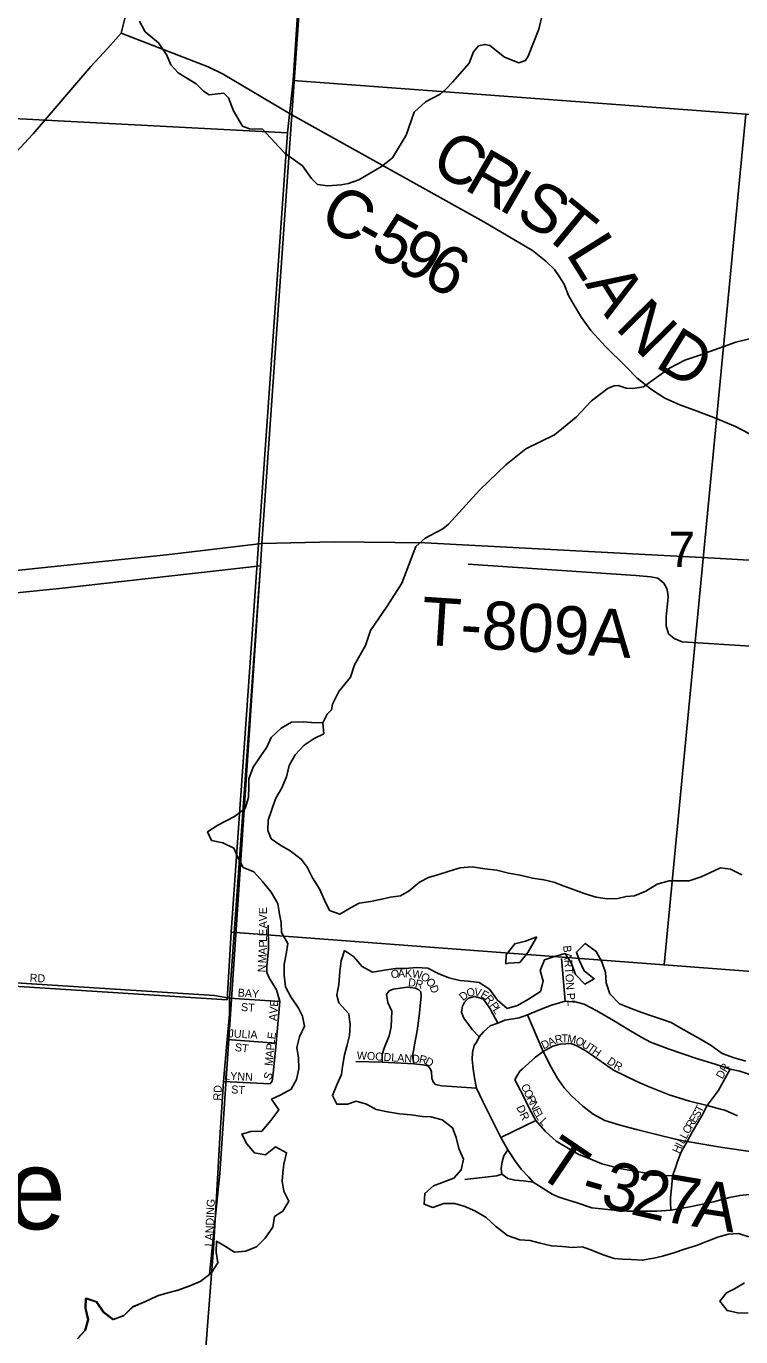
# Model space of a CAD drawing. Extents: x 0 to 40.4, y 0 to 22.
# Drawn here: x 7.886 to 8.731, y 15.17 to 16.72 of the extents above; entities that cross this region are included whole.
import ezdxf

# ---------------------------------------------------------------- set-up
doc = ezdxf.new("R2010")
doc.units = 0
for name, color, linetype in [('GM_X_City_Street', 7, 'Continuous'), ('GM_X_City_Street_Text', 7, 'Continuous'), ('GM_X_Corporation', 7, 'Continuous'), ('GM_X_County_Road', 7, 'Continuous'), ('GM_X_County_Road_Text', 7, 'Continuous'), ('GM_X_Interstate_Route', 7, 'Continuous'), ('GM_X_Major_Lake', 7, 'Continuous'), ('GM_X_Minor_Lake_Text', 7, 'Continuous'), ('GM_X_Minor_River', 7, 'Continuous'), ('GM_X_Section', 7, 'Continuous'), ('GM_X_Section_Text', 7, 'Continuous'), ('GM_X_Township', 7, 'Continuous'), ('GM_X_Township_Road', 7, 'Continuous'), ('GM_X_Township_Road_Text', 7, 'Continuous'), ('GM_X_Township_Subdivision', 7, 'Continuous'), ('GM_X_Township_Subdivision_Text', 7, 'Continuous')]:
    doc.layers.add(name, color=color, linetype=linetype)

msp = doc.modelspace()

# ---------------------------------------------------------------- linework, layer by layer
at = {"layer": 'GM_X_City_Street'}
msp.add_lwpolyline([(7.6176, 15.6748), (7.6167, 15.6381), (7.6129, 15.6192), (7.6135, 15.6152), (7.615, 15.6115), (7.6206, 15.6052), (7.6279, 15.6039), (7.781, 15.5944), (8.1089, 15.5735), (8.127, 15.57)], dxfattribs=at)
at = {"layer": 'GM_X_Corporation'}
msp.add_lwpolyline([(7.6362, 16.0259), (7.9257, 16.0548), (8.1633, 16.0818), (8.1154, 15.3626), (8.103, 15.2433), (8.0922, 15.2349), (8.0793, 15.2296), (8.0649, 15.2244), (8.0506, 15.2206), (8.0407, 15.2177), (8.0267, 15.2109), (8.0123, 15.2049), (8.0013, 15.1943), (7.9888, 15.1898), (7.9775, 15.1986), (7.9692, 15.2107), (7.9567, 15.2149), (7.9563, 15.2032), (7.9593, 15.1895), (7.9558, 15.177), (7.9467, 15.1672)], dxfattribs=at)
at = {"layer": 'GM_X_County_Road'}
for points in [[(7.9986, 16.7119), (8.0034, 16.7309), (8.0048, 16.7445), (8.0043, 16.7815), (8.0046, 16.7931), (8.0078, 16.8426), (8.0237, 17.0971)], [(7.636, 16.0217), (7.6362, 16.0259), (7.6375, 16.0515), (7.6454, 16.1992), (7.6518, 16.3027), (7.6559, 16.3343), (7.6592, 16.3572), (7.6643, 16.369), (7.6877, 16.3975), (7.7254, 16.4327), (7.7742, 16.4712), (7.7928, 16.4863), (7.8207, 16.5131), (7.853, 16.5482), (7.8946, 16.593), (7.9628, 16.6727), (7.983, 16.6943), (7.9986, 16.7119)], [(7.9986, 16.7119), (8.0843, 16.6791), (8.1017, 16.6721), (8.1194, 16.6635), (8.1977, 16.6171)], [(8.1977, 16.6171), (8.2004, 16.6154), (8.4276, 16.4886), (8.485, 16.4547), (8.5009, 16.4422), (8.5112, 16.4323), (8.5163, 16.4248), (8.5223, 16.4149), (8.5278, 16.4018), (8.5348, 16.3895), (8.5429, 16.3755), (8.5541, 16.3602), (8.5712, 16.3412), (8.595, 16.3181), (8.6088, 16.3038), (8.6259, 16.2903), (8.6416, 16.28), (8.6592, 16.2721), (8.6798, 16.2647), (8.7013, 16.2563), (8.725, 16.2467), (8.7589, 16.2289)], [(8.7525, 15.4765), (8.7302, 15.4837), (8.7187, 15.486), (8.7009, 15.4921), (8.6778, 15.4991), (8.6467, 15.5097), (8.6247, 15.5181), (8.6144, 15.5238), (8.5989, 15.5326), (8.581, 15.5437), (8.5613, 15.5553), (8.5461, 15.5631), (8.5372, 15.5653), (8.5235, 15.5668), (8.5077, 15.5621), (8.4935, 15.5565), (8.4792, 15.5503), (8.4691, 15.5471), (8.4524, 15.5442), (8.444, 15.5405), (8.4349, 15.5373), (8.4271, 15.5304), (8.4219, 15.5245), (8.4192, 15.5186), (8.4161, 15.5141), (8.414, 15.5058), (8.4138, 15.4975), (8.4148, 15.4866), (8.4165, 15.4758), (8.419, 15.4635), (8.4264, 15.4479), (8.439, 15.4225), (8.4431, 15.4141), (8.4478, 15.4055), (8.4559, 15.3907), (8.4649, 15.3768), (8.4715, 15.3679), (8.4806, 15.3583), (8.4859, 15.3525), (8.5082, 15.3384), (8.5154, 15.335), (8.5237, 15.3322), (8.5367, 15.3286), (8.5553, 15.322), (8.5816, 15.3193), (8.5974, 15.3181), (8.6321, 15.3182), (8.6488, 15.3193), (8.673, 15.3236), (8.6991, 15.3291), (8.7179, 15.3344), (8.7302, 15.3367), (8.7415, 15.338)]]:
    msp.add_lwpolyline(points, dxfattribs=at)
at = {"layer": 'GM_X_Interstate_Route'}
msp.add_lwpolyline([(7.7959, 16.068), (7.8971, 16.0785), (8.0522, 16.0948), (8.1652, 16.1082), (8.2508, 16.1101), (8.3578, 16.109), (8.7001, 16.0907), (8.8023, 16.0849), (8.8184, 16.0837)], dxfattribs=at)
at = {"layer": 'GM_X_Major_Lake'}
for points in [[(8.7325, 15.7162), (8.7193, 15.7227), (8.7072, 15.7246), (8.6947, 15.7186), (8.6844, 15.7137), (8.6704, 15.7092), (8.6606, 15.7089), (8.6466, 15.7089), (8.6326, 15.7052), (8.619, 15.6969), (8.6057, 15.6913), (8.5959, 15.6906), (8.586, 15.6883), (8.5732, 15.6876), (8.5603, 15.6896), (8.5463, 15.6942), (8.5324, 15.6991), (8.5225, 15.7026), (8.5101, 15.7076), (8.4984, 15.7103), (8.4851, 15.7122), (8.4704, 15.7157), (8.4568, 15.718), (8.4428, 15.7215), (8.4285, 15.7234), (8.4137, 15.7254), (8.3994, 15.7243), (8.3865, 15.7206), (8.3744, 15.7164), (8.3619, 15.7131), (8.3513, 15.7074), (8.3391, 15.6972), (8.3289, 15.6912), (8.3172, 15.6897), (8.3069, 15.6875), (8.2937, 15.6845), (8.2801, 15.6827), (8.2706, 15.6774), (8.2573, 15.6695), (8.2449, 15.6741), (8.2392, 15.6863), (8.2333, 15.6996), (8.225, 15.7125), (8.2186, 15.725), (8.2115, 15.7345), (8.1986, 15.7444), (8.1862, 15.7517), (8.176, 15.7589), (8.1723, 15.7684), (8.1727, 15.7809), (8.1765, 15.7923), (8.1811, 15.8059), (8.1887, 15.8192), (8.1941, 15.8321), (8.1972, 15.8453), (8.2044, 15.8582), (8.215, 15.8695), (8.2268, 15.8774), (8.2382, 15.8831), (8.2371, 15.896), (8.2238, 15.8964), (8.214, 15.8972), (8.2, 15.8969), (8.1879, 15.8897), (8.1761, 15.8788), (8.1708, 15.867), (8.1639, 15.8568), (8.1548, 15.8436), (8.1495, 15.8299), (8.1498, 15.8205), (8.1494, 15.8076), (8.1452, 15.7947), (8.1326, 15.7853), (8.1129, 15.7747), (8.1008, 15.7672), (8.1057, 15.7569), (8.1189, 15.7538), (8.1321, 15.7477), (8.1373, 15.7352), (8.143, 15.7249), (8.1554, 15.7196), (8.166, 15.7082), (8.1761, 15.6956)], [(8.1761, 15.6956), (8.184, 15.6823), (8.1859, 15.6694), (8.1877, 15.6599), (8.1884, 15.6478), (8.1956, 15.6349), (8.194, 15.6223), (8.1913, 15.6102), (8.1916, 15.5973), (8.1931, 15.5837), (8.1995, 15.5719), (8.2085, 15.5582), (8.2133, 15.5487), (8.2156, 15.5369), (8.2095, 15.5244), (8.2064, 15.5119), (8.2082, 15.4994), (8.2089, 15.4865), (8.2059, 15.474), (8.1998, 15.4627), (8.1876, 15.4559), (8.1763, 15.4506), (8.1853, 15.4381), (8.1758, 15.4256), (8.1651, 15.4127), (8.1519, 15.4124), (8.1413, 15.4094), (8.1473, 15.398), (8.1563, 15.387), (8.1692, 15.385), (8.181, 15.3941), (8.1942, 15.3872), (8.1911, 15.3736), (8.1899, 15.3637), (8.1891, 15.3535), (8.191, 15.3417), (8.197, 15.3299), (8.1897, 15.3182), (8.1799, 15.3118), (8.1779, 15.2993), (8.1688, 15.2861), (8.1589, 15.2759), (8.1457, 15.271), (8.1328, 15.2695), (8.1222, 15.2764), (8.1113, 15.2825), (8.1109, 15.2696), (8.1131, 15.2571), (8.1051, 15.2446), (8.093, 15.2352), (8.0801, 15.2299), (8.0657, 15.2247), (8.0513, 15.2209), (8.0415, 15.2179), (8.0274, 15.2111), (8.013, 15.2051), (8.002, 15.1946), (7.9895, 15.1901), (7.9782, 15.1988), (7.97, 15.211), (7.9575, 15.2152), (7.9571, 15.2035), (7.96, 15.1898), (7.9566, 15.1773), (7.9475, 15.1675)], [(8.7372, 15.4955), (8.7233, 15.4997), (8.7093, 15.5047), (8.6961, 15.5142), (8.6837, 15.5218), (8.6738, 15.5272), (8.6606, 15.5348), (8.6489, 15.5413), (8.6365, 15.5459), (8.6233, 15.5501), (8.6101, 15.5547), (8.5976, 15.5597), (8.5878, 15.5636), (8.5765, 15.5754), (8.572, 15.5883), (8.5713, 15.6004), (8.5672, 15.6133), (8.5604, 15.6255), (8.5472, 15.635), (8.537, 15.6248), (8.5403, 15.6153), (8.5463, 15.6024), (8.558, 15.5932), (8.547, 15.5868), (8.5357, 15.5983), (8.5312, 15.6112), (8.5237, 15.623), (8.5112, 15.6196), (8.4991, 15.6155), (8.4942, 15.603), (8.4975, 15.5904), (8.4944, 15.5779), (8.4804, 15.5689), (8.4675, 15.5617), (8.455, 15.558), (8.4437, 15.5679), (8.4343, 15.5808), (8.4219, 15.5888), (8.409, 15.5904), (8.3992, 15.5912), (8.3863, 15.5943), (8.3735, 15.5993), (8.3614, 15.6058), (8.3478, 15.6066), (8.3346, 15.6051), (8.3232, 15.6052), (8.31, 15.6033), (8.296, 15.6011), (8.2835, 15.6076), (8.2734, 15.6194), (8.2628, 15.6266)], [(8.4537, 15.6107), (8.4568, 15.6118), (8.47, 15.6122), (8.4795, 15.6243), (8.4902, 15.6428)], [(8.4902, 15.6428), (8.4769, 15.6376), (8.464, 15.6346), (8.4538, 15.6213), (8.4537, 15.6107)], [(8.2628, 15.6266), (8.259, 15.6145), (8.2571, 15.6016), (8.2559, 15.5865), (8.2539, 15.5739), (8.2561, 15.5645), (8.2678, 15.5515), (8.2693, 15.5386), (8.2685, 15.5261), (8.2654, 15.5132), (8.2627, 15.503), (8.2604, 15.4894), (8.2592, 15.4799), (8.2539, 15.4678), (8.2485, 15.4549), (8.2538, 15.4446), (8.2662, 15.4446), (8.2765, 15.4483), (8.2889, 15.4449), (8.3003, 15.4384), (8.3135, 15.4357), (8.3278, 15.4334), (8.3414, 15.4322), (8.3551, 15.4302), (8.3649, 15.4298), (8.3781, 15.4263), (8.3905, 15.4168), (8.3947, 15.4054), (8.398, 15.3925), (8.4036, 15.3796), (8.4009, 15.3671), (8.3922, 15.3573), (8.368, 15.3482), (8.3577, 15.3392), (8.3569, 15.3263), (8.3671, 15.3225), (8.3803, 15.3273), (8.3932, 15.3273), (8.4049, 15.3238), (8.417, 15.3185), (8.4302, 15.3108), (8.4415, 15.3006), (8.4554, 15.2895), (8.4702, 15.2841), (8.4823, 15.2833), (8.494, 15.2803), (8.5076, 15.2772), (8.5204, 15.2764), (8.5321, 15.2752), (8.5443, 15.2759), (8.556, 15.2717), (8.5688, 15.2663), (8.5816, 15.2621), (8.5915, 15.2613), (8.6017, 15.2609), (8.6149, 15.2601), (8.6285, 15.2627), (8.6387, 15.2649), (8.652, 15.269), (8.6649, 15.2732), (8.6789, 15.2776), (8.6921, 15.2825), (8.7043, 15.2874), (8.7164, 15.2908), (8.7285, 15.2919), (8.7409, 15.2876)], [(8.7358, 15.2334), (8.724, 15.2263), (8.7146, 15.2214), (8.7066, 15.2116), (8.7152, 15.2005), (8.7277, 15.1978), (8.7402, 15.1974)]]:
    msp.add_lwpolyline(points, dxfattribs=at)
at = {"layer": 'GM_X_Minor_River'}
for points in [[(8.0202, 16.7264), (8.027, 16.7138), (8.0428, 16.7005), (8.0526, 16.6861), (8.0575, 16.6744), (8.0662, 16.6652), (8.0873, 16.6519), (8.096, 16.6436), (8.1028, 16.639), (8.1202, 16.6409), (8.1255, 16.6355), (8.1315, 16.62), (8.1421, 16.6021), (8.1504, 16.5987), (8.1659, 16.5983), (8.1851, 16.5774), (8.1923, 16.5702), (8.2131, 16.555), (8.2236, 16.5402), (8.2308, 16.533), (8.2429, 16.5314), (8.2588, 16.5325), (8.2675, 16.534), (8.2796, 16.5386), (8.3064, 16.5541), (8.3197, 16.5646), (8.3356, 16.5915), (8.3451, 16.6184), (8.3584, 16.6306), (8.3758, 16.64), (8.3826, 16.6457), (8.3906, 16.654), (8.4103, 16.6767), (8.4152, 16.69), (8.4213, 16.6972), (8.4285, 16.6987), (8.4345, 16.6975), (8.4519, 16.6838), (8.4689, 16.677), (8.4768, 16.6796), (8.4799, 16.6849), (8.4924, 16.7167), (8.4989, 16.7433)], [(8.2371, 15.896), (8.2424, 15.9061), (8.2473, 15.9114), (8.2485, 15.9179), (8.2561, 15.933), (8.2697, 15.9501), (8.2747, 15.9645), (8.2876, 15.9876), (8.2936, 16.0054), (8.3134, 16.0342), (8.3304, 16.0611), (8.3472, 16.1046), (8.3581, 16.1145), (8.379, 16.1254), (8.3858, 16.1311), (8.4229, 16.1716), (8.4331, 16.1814), (8.4536, 16.2011), (8.4771, 16.22), (8.5111, 16.2367), (8.5365, 16.2578), (8.5547, 16.2768), (8.5744, 16.2919), (8.5816, 16.2949), (8.5865, 16.2953), (8.5959, 16.2919), (8.6039, 16.2915), (8.6163, 16.2937), (8.647, 16.3157), (8.6652, 16.3251), (8.6841, 16.3315), (8.6905, 16.3338), (8.7253, 16.3466), (8.7548, 16.3537)]]:
    msp.add_lwpolyline(points, dxfattribs=at)
at = {"layer": 'GM_X_Section'}
for points in [[(7.3378, 17.2417), (7.7228, 17.2207), (8.2373, 17.1912), (8.202, 16.6562), (8.1953, 16.5941), (7.7054, 16.6198), (7.2909, 16.6427)], [(8.2373, 17.1912), (9.2326, 17.1127), (9.1966, 16.5816), (8.7372, 16.616), (8.202, 16.6562)], [(8.202, 16.6562), (8.7372, 16.616), (8.6406, 15.6095), (8.1289, 15.6484), (8.1953, 16.5941)], [(7.7054, 16.6198), (8.1953, 16.5941), (8.1289, 15.6484), (8.124, 15.5684), (7.6314, 15.5996)], [(8.7372, 16.616), (9.1966, 16.5816), (9.1227, 15.573), (8.6406, 15.6095)]]:
    msp.add_lwpolyline(points, close=True, dxfattribs=at)
at = {"layer": 'GM_X_Township'}
msp.add_lwpolyline([(8.0846, 14.9692), (8.096, 15.1213), (8.108, 15.2741), (8.1112, 15.3285), (8.1141, 15.384), (8.1155, 15.405), (8.1199, 15.4715), (8.1241, 15.5213), (8.1269, 15.5514), (8.127, 15.57), (8.1633, 16.0818), (8.1652, 16.1082), (8.2004, 16.6154), (8.2342, 17.0906), (8.241, 17.1909), (8.1794, 17.1936), (7.7202, 17.2134)], dxfattribs=at)
at = {"layer": 'GM_X_Township_Road'}
for points in [[(8.749, 15.9863), (8.662, 15.9918), (8.6524, 15.9956), (8.646, 16.0013), (8.6429, 16.0107), (8.6429, 16.0213), (8.6442, 16.0333), (8.6453, 16.0446), (8.6451, 16.0489), (8.6438, 16.0548), (8.6402, 16.0613), (8.6334, 16.0671), (8.6251, 16.0686), (8.6072, 16.0704), (8.4089, 16.0836)], [(8.6653, 15.401), (8.654, 15.4033), (8.6317, 15.409), (8.608, 15.4148), (8.5886, 15.42), (8.5705, 15.4254), (8.5569, 15.4329), (8.5447, 15.4423), (8.5309, 15.4549), (8.5224, 15.4641), (8.5141, 15.4758), (8.507, 15.4886), (8.4976, 15.5071), (8.4792, 15.5503)], [(8.8327, 15.3739), (8.8163, 15.3781), (8.7096, 15.3935), (8.6678, 15.4005), (8.6653, 15.401)]]:
    msp.add_lwpolyline(points, dxfattribs=at)
at = {"layer": 'GM_X_Township_Subdivision'}
for points in [[(8.1862, 15.5664), (8.1824, 15.5799), (8.1738, 15.5941), (8.1709, 15.6005), (8.1709, 15.6075), (8.1728, 15.6283), (8.1726, 15.6566)], [(8.5235, 15.5668), (8.5195, 15.617)], [(8.108, 15.2741), (8.1112, 15.3285), (8.1141, 15.384), (8.1155, 15.405), (8.1199, 15.4715), (8.1241, 15.5213), (8.1269, 15.5514), (8.127, 15.57)], [(8.127, 15.57), (8.1862, 15.5664)], [(8.3073, 15.4946), (8.3075, 15.5034), (8.3096, 15.511), (8.3157, 15.5256), (8.3179, 15.5364), (8.3184, 15.5454), (8.3186, 15.555), (8.314, 15.565), (8.3125, 15.5746), (8.3154, 15.5788), (8.3202, 15.5809), (8.3369, 15.5833), (8.3434, 15.5824)], [(8.3434, 15.5824), (8.3469, 15.582), (8.3505, 15.5802), (8.353, 15.5775), (8.3534, 15.5725), (8.3512, 15.5492), (8.3486, 15.5316), (8.3456, 15.5148), (8.3446, 15.5099), (8.3433, 15.502), (8.3448, 15.4924)], [(8.444, 15.5405), (8.4349, 15.5575), (8.429, 15.5661), (8.4263, 15.5695), (8.4165, 15.5722), (8.4094, 15.5703), (8.4045, 15.5656), (8.4022, 15.5609), (8.401, 15.5538), (8.4037, 15.5466), (8.4096, 15.5385), (8.4143, 15.5326), (8.4219, 15.5245)], [(8.1748, 15.4687), (8.1774, 15.4718), (8.1783, 15.481), (8.1819, 15.5171), (8.1862, 15.5664)], [(8.1241, 15.5213), (8.1819, 15.5171)], [(8.4976, 15.5071), (8.5092, 15.5132), (8.5178, 15.5159), (8.5244, 15.5161), (8.5306, 15.5164), (8.5375, 15.5139), (8.548, 15.508), (8.5623, 15.4982), (8.581, 15.4849), (8.6083, 15.4716), (8.6211, 15.466), (8.6467, 15.4557), (8.6706, 15.4484), (8.6915, 15.443), (8.7072, 15.4389)], [(8.2762, 15.4951), (8.3073, 15.4946), (8.3448, 15.4924), (8.3555, 15.4914), (8.3612, 15.4903), (8.364, 15.4868), (8.3656, 15.4829), (8.366, 15.4757), (8.3675, 15.4712), (8.3704, 15.468), (8.378, 15.4664), (8.419, 15.4635)], [(8.6507, 15.3599), (8.6273, 15.3609), (8.6174, 15.3635), (8.5902, 15.3681), (8.567, 15.3741), (8.5511, 15.381), (8.54, 15.3852), (8.5296, 15.3912), (8.513, 15.401), (8.5005, 15.4123), (8.489, 15.4256), (8.4809, 15.441), (8.4735, 15.4558), (8.4642, 15.4735), (8.4665, 15.478), (8.4699, 15.4837), (8.473, 15.4863), (8.4885, 15.5004), (8.4976, 15.5071)], [(8.6488, 15.3193), (8.6483, 15.3283), (8.6483, 15.3342), (8.6496, 15.3494), (8.6507, 15.3599), (8.654, 15.3693), (8.656, 15.3757), (8.661, 15.3883), (8.6678, 15.4005), (8.6739, 15.4118), (8.6854, 15.4308), (8.6915, 15.443), (8.7045, 15.4607), (8.7187, 15.486)], [(8.1199, 15.4715), (8.1748, 15.4687)], [(8.7072, 15.4389), (8.7124, 15.4376), (8.7274, 15.4308)], [(8.4478, 15.4055), (8.489, 15.4256)], [(8.4859, 15.3525), (8.4743, 15.3542), (8.4643, 15.3549), (8.4559, 15.3568), (8.4489, 15.362), (8.4482, 15.3685), (8.449, 15.3765), (8.451, 15.3838), (8.4559, 15.3907)], [(8.4052, 15.3557), (8.4427, 15.3599), (8.4489, 15.362)]]:
    msp.add_lwpolyline(points, dxfattribs=at)

# ---------------------------------------------------------------- texts
at = {"layer": 'GM_X_City_Street_Text'}
msp.add_text('RD', height=0.00947, rotation=356.989, dxfattribs=at).set_placement((7.8904, 15.5897))
at = {"layer": 'GM_X_County_Road_Text'}
for s, rotation, p in [('C', 329.9734, (8.362, 16.5516)), ('R', 329.9804, (8.4024, 16.5283)), ('I', 329.9385, (8.4428, 16.5049)), ('S', 329.3068, (8.4629, 16.4933)), ('C', 330.5712, (8.2301, 16.4869)), ('T', 320.5999, (8.494, 16.4751)), ('5', 330.58, (8.2911, 16.4525)), ('-', 330.5678, (8.2708, 16.464)), ('9', 330.627, (8.3216, 16.4353)), ('L', 302.1685, (8.5236, 16.4517)), ('6', 330.8212, (8.3523, 16.418)), ('A', 302.3802, (8.5464, 16.4155)), ('N', 314.8183, (8.5815, 16.3628)), ('D', 328.424, (8.6283, 16.3182))]:
    msp.add_text(s, height=0.0568, rotation=rotation, dxfattribs=at).set_placement(p)
at = {"layer": 'GM_X_Minor_Lake_Text'}
msp.add_text('Crane', height=0.09469, rotation=0.0002, dxfattribs=at).set_placement((7.5885, 15.2968))
at = {"layer": 'GM_X_Section_Text'}
msp.add_text('7', height=0.0419, rotation=0, dxfattribs=at).set_placement((8.6461, 16.0802))
at = {"layer": 'GM_X_Township_Road_Text'}
for s, height, rotation, p in [('T-809A', 0.05682, 356.316, (8.3523, 15.9886)), ('T', 0.0568, 325.8808, (8.4868, 15.3633)), ('3', 0.0568, 345.3354, (8.5635, 15.3243)), ('2', 0.0568, 347.1468, (8.5992, 15.315)), ('-', 0.0568, 343.7999, (8.5394, 15.3313)), ('7', 0.0568, 350.3978, (8.6368, 15.3065)), ('A', 0.0568, 351.3824, (8.6724, 15.3005))]:
    msp.add_text(s, height=height, rotation=rotation, dxfattribs=at).set_placement(p)
at = {"layer": 'GM_X_Township_Subdivision_Text'}
for s, rotation, p in [('V', 89.9928, (8.171, 15.6611)), ('E', 89.9956, (8.171, 15.6694)), ('A', 89.9928, (8.171, 15.6528)), ('E', 89.9956, (8.171, 15.6436)), ('P', 89.5695, (8.171, 15.6302)), ('L', 89.9956, (8.171, 15.6369)), ('BARTON PL', 274.456, (8.5212, 15.6322)), ('M', 86.6613, (8.17, 15.6113)), ('A', 87.3582, (8.1706, 15.6214)), ('N', 86.6541, (8.1694, 15.6005)), ('O', 3.7835, (8.3178, 15.5939)), ('A', 3.7617, (8.3261, 15.5944)), ('K', 359.3005, (8.3342, 15.595)), ('W', 350.6261, (8.3422, 15.5949)), ('D', 353.626, (8.3376, 15.5845)), ('R', 344.5149, (8.3455, 15.5836)), ('O', 326.5464, (8.3519, 15.5935)), ('O', 309.2879, (8.3583, 15.5894)), ('D', 289.1261, (8.3632, 15.5837)), ('BAY', 356.0574, (8.1363, 15.5722)), ('D', 40.0939, (8.4031, 15.5665)), ('O', 15.0328, (8.4085, 15.5714)), ('V', 348.2486, (8.4154, 15.5735)), ('E', 330.0484, (8.4228, 15.5721)), ('R', 310.1693, (8.4279, 15.5693)), ('ST', 356.4262, (8.1402, 15.5551)), ('AVE', 85.9166, (8.1827, 15.543)), ('P', 303.9174, (8.434, 15.5618)), ('L', 300.7717, (8.4377, 15.5564)), ('JULIA', 357.0602, (8.1254, 15.5239)), ('E', 81.9395, (8.1808, 15.5211)), ('A', 23.3277, (8.5054, 15.513)), ('R', 13.5297, (8.5127, 15.5161)), ('T', 1.202, (8.5194, 15.5178)), ('M', 350.8371, (8.5256, 15.518)), ('O', 335.0966, (8.5348, 15.5166)), ('ST', 352.8649, (8.1327, 15.5077)), ('A', 84.77, (8.1786, 15.4997)), ('P', 84.6646, (8.1794, 15.508)), ('L', 83.2071, (8.18, 15.5146)), ('D', 24.5507, (8.4979, 15.5095)), ('U', 329.0512, (8.5422, 15.5132)), ('T', 325.431, (8.5492, 15.509)), ('H', 325.488, (8.5547, 15.5052)), ('M', 84.766, (8.1777, 15.4897)), ('WOODLAND', 356.4666, (8.2771, 15.498)), ('R', 347.9612, (8.3504, 15.4939)), ('D', 332.8583, (8.3571, 15.4925)), ('D', 324.6427, (8.5723, 15.4935)), ('R', 332.3116, (8.5802, 15.4879)), ('DR', 60.6435, (8.7096, 15.4738)), ('LYNN', 357.0658, (8.1204, 15.4739)), ('S', 69.9888, (8.1755, 15.4726)), ('RD', 86.9775, (8.1169, 15.4488)), ('ST', 356.4262, (8.1286, 15.4576)), ('C', 295.6962, (8.4711, 15.4662)), ('O', 295.7037, (8.4743, 15.4594)), ('R', 295.7163, (8.4779, 15.4519)), ('N', 295.7049, (8.4812, 15.4452)), ('DR', 295.1968, (8.4657, 15.441)), ('E', 295.6906, (8.4848, 15.4376)), ('L', 301.9006, (8.4882, 15.4307)), ('E', 57.7195, (8.6775, 15.4215)), ('S', 60.4082, (8.6813, 15.4275)), ('T', 64.4922, (8.6849, 15.434)), ('L', 312.2898, (8.4929, 15.4235)), ('C', 60.6647, (8.6699, 15.4087)), ('R', 57.92, (8.6735, 15.4151)), ('I', 63.0439, (8.6619, 15.3932)), ('L', 62.5798, (8.6638, 15.3969)), ('L', 62.5673, (8.6669, 15.4028)), ('H', 65.5958, (8.6585, 15.3857)), ('LANDING', 87.2752, (8.1069, 15.2763))]:
    msp.add_text(s, height=0.00947, rotation=rotation, dxfattribs=at).set_placement(p)

doc.saveas('drawing.dxf')
